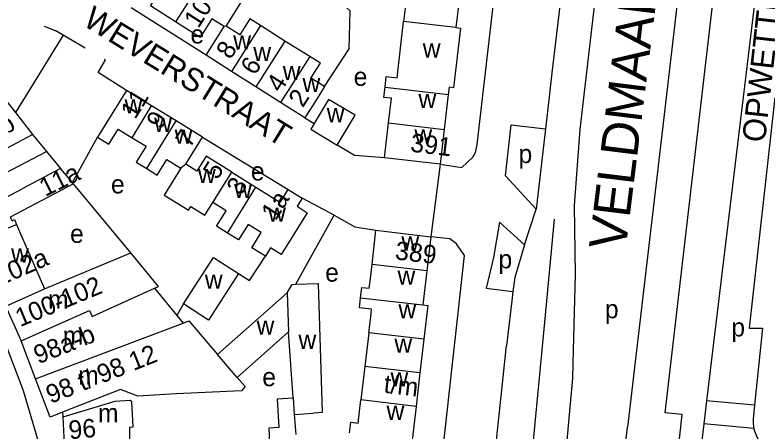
# Model space of a CAD drawing. Extents: x 159902 to 161769, y 383692 to 384875.
# Drawn here: x 161124 to 161287.3, y 384324.5 to 384414.9 of the extents above; entities that cross this region are included whole.
import ezdxf

# ---------------------------------------------------------------- set-up
doc = ezdxf.new("R2010")
doc.units = 0
for name, color, linetype in [('BLT_Basislijn', 7, 'Continuous'), ('BLT_Bebouwing', 7, 'Continuous'), ('BLT_Centroide', 7, 'Continuous'), ('BLT_Huisnummer', 7, 'Continuous'), ('BLT_Huisnummer_ tussenligend', 7, 'Continuous'), ('BLT_Huisnummer_reeks', 7, 'Continuous'), ('BLT_Onderverdeling_panden', 7, 'Continuous'), ('BLT_Straatnaam', 7, 'Continuous'), ('BLT_Straatnaam_hoofdweg', 7, 'Continuous'), ('BLT_Vlakafsluiter', 7, 'Continuous')]:
    doc.layers.add(name, color=color, linetype=linetype)

msp = doc.modelspace()

# ---------------------------------------------------------------- linework, layer by layer
at = {"layer": 'BLT_Basislijn'}
for p, q in [((161271.76, 384452.91), (161264.31, 384389.57)), ((161288.54, 384452.1), (161273.96, 384331.2)), ((161245.38, 384444.89), (161240.42, 384402.37)), ((161252.52, 384442.13), (161246.47, 384390.06)), ((161165.41, 384406.2), (161149.2, 384416.48)), ((161130.28, 384412.54), (161132.67, 384411.6)), ((161134.42, 384410.57), (161124.12, 384393.8)), ((161134.42, 384410.57), (161132.67, 384411.6)), ((161139.21, 384407.76), (161134.42, 384410.57)), ((161240.42, 384402.37), (161239.8, 384397.16)), ((161186.81, 384392.6), (161188.83, 384391.35)), ((161264.31, 384389.57), (161256.78, 384325.49)), ((161136.45, 384378.58), (161141.87, 384388.39)), ((161164.65, 384388.44), (161183.21, 384377.06)), ((161149.12, 384363.32), (161136.67, 384378.32)), ((161193.2, 384371.49), (161186.25, 384375.2)), ((161184.9, 384356.49), (161193.2, 384371.49)), ((161231.98, 384354.91), (161231.71, 384352.88)), ((161160.51, 384352.23), (161159.06, 384349.75)), ((161231.71, 384352.88), (161230.58, 384343.23)), ((161286.06, 384346.97), (161284.36, 384330.24)), ((161226.83, 384308.12), (161230.58, 384343.23)), ((161273.96, 384331.2), (161273.36, 384326.24)), ((161284.36, 384330.24), (161273.96, 384331.2)), ((161284.36, 384330.24), (161284.05, 384327.2)), ((161134.27, 384328.72), (161134.33, 384327.66)), ((161255.4, 384313.8), (161256.78, 384325.49)), ((161284.22, 384325.23), (161273.36, 384326.24))]:
    msp.add_line(p, q, dxfattribs=at)
for points in [[(161216.18, 384382.54), (161220.92, 384381.86), (161223.28, 384384.11), (161223.85, 384385.06), (161224.2, 384386.82), (161237.3, 384500)], [(161262.33, 384305.37), (161262.7, 384308.11), (161266.42, 384307.7), (161268.65, 384328.26), (161265, 384328.62), (161268.94, 384362.86), (161276.08, 384424.55)], [(161191.11, 384399.38), (161196.48, 384407.62), (161196.66, 384415.85), (161195.11, 384417.26)], [(161148.2, 384398.55), (161142.02, 384402.45), (161143.61, 384405.17), (161143.4, 384405.29)], [(161091.04, 384402.68), (161092.89, 384399.78), (161106.05, 384377.98), (161112.13, 384366.07), (161119.42, 384350), (161125.75, 384333.48), (161131.82, 384312.82), (161133.22, 384304.1)], [(161239.8, 384397.16), (161239.01, 384390.24)], [(161288.75, 384397.06), (161283.22, 384346.97), (161286.06, 384346.97)], [(161230.32, 384380.03), (161231.61, 384391.1), (161239.01, 384390.24)], [(161239.01, 384390.24), (161237.03, 384372.81)], [(161246.47, 384390.06), (161245.28, 384373.6), (161245.45, 384358.6), (161245.06, 384342.19), (161244.91, 384336.11), (161242.28, 384307.53)], [(161204.11, 384383.95), (161197.64, 384384.44), (161193.88, 384386.71)], [(161237.03, 384372.81), (161230.32, 384380.03)], [(161193.2, 384371.49), (161197.65, 384368.98), (161202.25, 384368.21)], [(161229.02, 384370), (161227.78, 384362.34), (161226.15, 384355.63), (161231.98, 384354.91)], [(161229.02, 384370), (161234.51, 384365.06)], [(161240.93, 384370.62), (161238.81, 384348.25), (161235.01, 384308.19)], [(161214.46, 384299.39), (161221.43, 384362.75), (161219.74, 384365.24), (161218.3, 384366.34), (161214.15, 384366.82)], [(161234.51, 384365.06), (161232.39, 384357.99), (161231.98, 384354.91)], [(161172.46, 384358.83), (161174.81, 384357.34), (161178.28, 384362.59)], [(161284.05, 384327.2), (161284.05, 384326.42), (161284.14, 384325.64), (161284.22, 384325.23)], [(161273.36, 384326.24), (161270.83, 384305.27), (161270.5, 384302.24)], [(161284.22, 384325.23), (161284.3, 384324.87), (161284.54, 384324.13), (161284.85, 384323.42), (161285.24, 384322.74), (161285.69, 384322.1)]]:
    msp.add_lwpolyline(points, dxfattribs=at)
at = {"layer": 'BLT_Bebouwing'}
for p, q in [((161209.36, 384422.73), (161208.27, 384413.52)), ((161220.64, 384421.12), (161219.6, 384412.2)), ((161165.41, 384406.2), (161169.35, 384412.4)), ((161169.78, 384412.51), (161169.35, 384412.4)), ((161182.53, 384409.25), (161177.22, 384412.62)), ((161187.91, 384405.95), (161182.53, 384409.25)), ((161113.42, 384406.78), (161124.12, 384393.8)), ((161170.92, 384402.7), (161165.41, 384406.2)), ((161176.23, 384399.33), (161170.92, 384402.7)), ((161181.55, 384395.95), (161176.23, 384399.33)), ((161148.2, 384398.55), (161141.87, 384388.39)), ((161153.62, 384395.21), (161148.2, 384398.55)), ((161217.95, 384397.67), (161217.07, 384390.11)), ((161186.81, 384392.6), (161181.55, 384395.95)), ((161124.12, 384393.8), (161127.77, 384389.01)), ((161158.92, 384391.96), (161153.62, 384395.21)), ((161164.65, 384388.44), (161158.92, 384391.96)), ((161204.11, 384383.95), (161204.99, 384391.52)), ((161127.77, 384389.01), (161130.81, 384385.33)), ((161217.07, 384390.11), (161216.18, 384382.54)), ((161161.02, 384382.53), (161164.65, 384388.44)), ((161216.18, 384382.54), (161204.11, 384383.95)), ((161136.45, 384378.58), (161133.87, 384381.64)), ((161170.99, 384380.82), (161176.2, 384377.57)), ((161136.67, 384378.32), (161136.45, 384378.58)), ((161176.2, 384377.57), (161181.41, 384374.31)), ((161183.21, 384377.06), (161186.25, 384375.2)), ((161201.41, 384360.78), (161202.25, 384368.21)), ((161202.25, 384368.21), (161214.15, 384366.82)), ((161214.15, 384366.82), (161213.31, 384359.42)), ((161130.37, 384355.54), (161149.12, 384363.32)), ((161213.31, 384359.42), (161212.46, 384352.02)), ((161154.24, 384355.65), (161159.06, 384349.75)), ((161167.92, 384341.26), (161183, 384354.63)), ((161212.46, 384352.02), (161213.51, 384351.9)), ((161213.51, 384351.9), (161212.66, 384344.6)), ((161159.06, 384349.75), (161160.44, 384348.07)), ((161183.32, 384346.15), (161172.2, 384336.26)), ((161200.72, 384345.99), (161199.86, 384338.69)), ((161128.46, 384335.95), (161125.29, 384344.24)), ((161212.66, 384344.6), (161211.81, 384337.3)), ((161199.86, 384338.69), (161198.99, 384331.4)), ((161211.81, 384337.3), (161210.96, 384330)), ((161184.56, 384328.22), (161188.74, 384328.51)), ((161210.96, 384330), (161210.11, 384322.7)), ((161134.33, 384327.66), (161134.68, 384321.86)), ((161184.56, 384328.22), (161184.86, 384323.88))]:
    msp.add_line(p, q, dxfattribs=at)
for points in [[(161158.8, 384413.44), (161153.37, 384416.89), (161155.14, 384419.68), (161152.24, 384421.52)], [(161169.78, 384412.51), (161173.35, 384418.13), (161168.1, 384421.46), (161166.04, 384418.22), (161163.05, 384420.12)], [(161169.35, 384412.4), (161166.67, 384414.1), (161164.11, 384410.07), (161158.8, 384413.44)], [(161177.22, 384412.62), (161174.92, 384414.09), (161172.73, 384410.64), (161169.78, 384412.51)], [(161204.25, 384399.3), (161204.51, 384401.55), (161206.84, 384401.28), (161208.27, 384413.52)], [(161219.6, 384412.2), (161220.57, 384412.09), (161219.06, 384399.14), (161218.14, 384399.24), (161217.95, 384397.67)], [(161191.11, 384399.38), (161188.17, 384401.24), (161190.23, 384404.48), (161187.91, 384405.95)], [(161191.11, 384399.38), (161189.49, 384396.82), (161186.81, 384392.6)], [(161204.99, 384391.52), (161205.62, 384396.87), (161203.98, 384397.05), (161204.25, 384399.3)], [(161193.88, 384386.71), (161197.73, 384393.16), (161191.97, 384396.61), (161188.83, 384391.35)], [(161188.83, 384391.35), (161188.11, 384390.15), (161193.88, 384386.71)], [(161141.87, 384388.39), (161144.34, 384386.87), (161146.35, 384390.16), (161149.38, 384388.3)], [(161149.38, 384388.3), (161152.4, 384386.44), (161150.28, 384383), (161152.56, 384381.6)], [(161130.81, 384385.33), (161133.87, 384381.64)], [(161170.99, 384380.82), (161165.42, 384384.3), (161163.42, 384381.05), (161161.02, 384382.53)], [(161152.56, 384381.6), (161154.84, 384380.2), (161156.92, 384383.59), (161159.97, 384381.71)], [(161159.97, 384381.71), (161156.36, 384375.83), (161160.62, 384373.22), (161161.62, 384372.6), (161162.1, 384373.37), (161165.14, 384371.47), (161166.88, 384374.25)], [(161136.67, 384378.32), (161122.92, 384371.04), (161123.36, 384370.3), (161123.87, 384370.54), (161124.34, 384369.48)], [(161181.41, 384374.31), (161181.5, 384374.25), (161183.21, 384377.06)], [(161170.09, 384367.62), (161167.7, 384369.09), (161169.78, 384372.47), (161166.88, 384374.25)], [(161186.25, 384375.2), (161185.15, 384373.42), (161187.36, 384372.02), (161184.71, 384367.78), (161181.7, 384362.96), (161179.38, 384364.38), (161178.28, 384362.59)], [(161124.34, 384369.48), (161124.44, 384369.12), (161130.37, 384355.54)], [(161177.37, 384367.74), (161174.52, 384369.49), (161172.47, 384366.15), (161170.09, 384367.62)], [(161178.28, 384362.59), (161175.32, 384364.41), (161177.37, 384367.74)], [(161154.24, 384355.65), (161155.11, 384356.05), (161149.12, 384363.32)], [(161160.51, 384352.23), (161167.04, 384362.33), (161172.46, 384358.83)], [(161198.92, 384353.59), (161199.18, 384355.81), (161200.82, 384355.62), (161201, 384357.16), (161201.41, 384360.78)], [(161172.46, 384358.83), (161165.93, 384348.72), (161160.51, 384352.23)], [(161183, 384354.63), (161184.07, 384356.47), (161184.9, 384356.49)], [(161184.9, 384356.49), (161189.74, 384356.64), (161190.59, 384328.64), (161188.74, 384328.51)], [(161200.72, 384345.99), (161201.13, 384349.44), (161201.32, 384351.07), (161198.66, 384351.38), (161198.92, 384353.59)], [(161125.29, 384344.24), (161125.23, 384344.41), (161122.03, 384351.76)], [(161160.44, 384348.07), (161161.69, 384348.54), (161167.92, 384341.26)], [(161184.31, 384331.83), (161183.32, 384346.15)], [(161134.27, 384328.72), (161131.63, 384327.67), (161128.46, 384335.95)], [(161172.2, 384336.26), (161173.88, 384334.3), (161173.09, 384333.4), (161158.96, 384332.72), (161150.64, 384332.2), (161146.84, 384333.69), (161136.28, 384329.51), (161134.27, 384328.72)], [(161180.81, 384331.62), (161184.31, 384331.83)], [(161148.98, 384331.27), (161145.65, 384331.08), (161134.33, 384327.66)], [(161148.74, 384322.98), (161148.87, 384322.99), (161148.86, 384325.48), (161149.63, 384325.53), (161149.33, 384331.01), (161148.98, 384331.27)], [(161180.81, 384331.62), (161181.18, 384325.43), (161179, 384325.29), (161179.19, 384322.2)], [(161196.52, 384324.28), (161196.78, 384326.55), (161198.39, 384326.36), (161198.99, 384331.4)]]:
    msp.add_lwpolyline(points, dxfattribs=at)
at = {"layer": 'BLT_Onderverdeling_panden'}
for p, q in [((161163.05, 384420.12), (161158.8, 384413.44)), ((161219.6, 384412.2), (161208.27, 384413.52)), ((161177.22, 384412.62), (161170.92, 384402.7)), ((161182.53, 384409.25), (161176.23, 384399.33)), ((161187.91, 384405.95), (161181.55, 384395.95)), ((161204.25, 384399.3), (161217.95, 384397.67)), ((161149.38, 384388.3), (161153.62, 384395.21)), ((161152.56, 384381.6), (161158.92, 384391.96)), ((161204.99, 384391.52), (161217.07, 384390.11)), ((161111.12, 384375.04), (161130.81, 384385.33)), ((161161.02, 384382.53), (161159.97, 384381.71)), ((161166.88, 384374.25), (161170.99, 384380.82)), ((161170.09, 384367.62), (161176.2, 384377.57)), ((161113.32, 384370.83), (161125.51, 384377.2)), ((161115.79, 384366.12), (161124.34, 384369.48)), ((161213.31, 384359.42), (161201.41, 384360.78)), ((161122.03, 384351.76), (161130.37, 384355.54)), ((161183, 384354.63), (161183.32, 384346.15)), ((161198.92, 384353.59), (161212.46, 384352.02)), ((161128.46, 384335.95), (161160.44, 384348.07)), ((161212.66, 384344.6), (161200.72, 384345.99)), ((161172.2, 384336.26), (161167.92, 384341.26)), ((161211.81, 384337.3), (161199.86, 384338.69)), ((161184.31, 384331.83), (161184.56, 384328.22)), ((161210.96, 384330), (161198.99, 384331.4))]:
    msp.add_line(p, q, dxfattribs=at)
for points in [[(161108.6, 384379.66), (161115.33, 384382.43), (161127.77, 384389.01)], [(161133.87, 384381.64), (161125.51, 384377.2)], [(161125.29, 384344.24), (161140.17, 384350.79), (161140.69, 384349.52), (161154.24, 384355.65)]]:
    msp.add_lwpolyline(points, dxfattribs=at)
at = {"layer": 'BLT_Vlakafsluiter'}
for p, q in [((161216.18, 384382.54), (161214.15, 384366.82)), ((161234.51, 384365.06), (161237.03, 384372.81))]:
    msp.add_line(p, q, dxfattribs=at)

# ---------------------------------------------------------------- texts
at = {"layer": 'BLT_Centroide'}
for s, p in [('e', (161162.04, 384408.74)), ('w', (161171.31, 384407.42)), ('w', (161212.41, 384405.69)), ('w', (161175.66, 384404.92)), ('w', (161182.06, 384400.8)), ('e', (161197.43, 384399.56)), ('w', (161186.33, 384398.19)), ('w', (161211.48, 384394.72)), ('w', (161147.75, 384393.58)), ('w', (161191.59, 384391.66)), ('w', (161154.16, 384389.55)), ('w', (161158.61, 384387)), ('w', (161210.59, 384387.03)), ('p', (161233.18, 384382.8)), ('w', (161163.66, 384378.44)), ('e', (161175.14, 384379.02)), ('e', (161144.8, 384376.22)), ('w', (161171.5, 384375.2)), ('w', (161178.87, 384370.06)), ('e', (161135.93, 384365.48)), ('w', (161207.78, 384363.81)), ('w', (161123.14, 384361.22)), ('p', (161228.83, 384359.95)), ('e', (161191.25, 384357.07)), ('w', (161206.94, 384356.41)), ('w', (161165.15, 384355.53)), ('m', (161131.15, 384351.22)), ('w', (161207.14, 384349.09)), ('p', (161251.91, 384349.12)), ('w', (161176.37, 384345.56)), ('p', (161279.33, 384345.17)), ('m', (161134.35, 384343.38)), ('w', (161185.46, 384342.47)), ('w', (161206.26, 384341.66)), ('m', (161137.68, 384334.75)), ('e', (161177.61, 384334.39)), ('w', (161205.41, 384334.34)), ('w', (161204.55, 384327.06)), ('m', (161141.98, 384326.56))]:
    msp.add_text(s, height=4, dxfattribs=at).set_placement(p)
at = {"layer": 'BLT_Huisnummer'}
for s, rotation, p in [('6', 57.5716, (161176.01, 384401.64)), ('2', 57.5684, (161186.41, 384394.66)), ('11', 58.4286, (161150.04, 384392.12)), ('7', 58.4301, (161161.92, 384385.89)), ('5', 58.4301, (161167.88, 384378.98)), ('1a', 58.0043, (161180.5, 384370.09)), ('102a', 23.5543, (161120.71, 384356.1)), ('96', 5.1333, (161135.79, 384322.86))]:
    msp.add_text(s, height=4, rotation=rotation, dxfattribs=at).set_placement(p)
at = {"layer": 'BLT_Huisnummer_ tussenligend'}
for s, rotation, p in [('8', 57.5673, (161170.71, 384405.1)), ('4', 57.5684, (161181.6, 384397.91)), ('9', 58.4212, (161155.61, 384389.92)), ('3', 58.0043, (161172.99, 384375.58))]:
    msp.add_text(s, height=4, rotation=rotation, dxfattribs=at).set_placement(p)
at = {"layer": 'BLT_Huisnummer_reeks'}
for s, rotation, p in [('10-a t/m e', 57.5638, (161163.75, 384411.87)), ('108-a-b', 30.9568, (161108.57, 384380.83)), ('391', 353.3491, (161209.58, 384385.29)), ('11a', 26.3835, (161130.53, 384375.43)), ('389', 353.4886, (161206.29, 384361.9)), ('100-102', 22.5543, (161125.1, 384347.18)), ('98a-b', 21.6602, (161129.02, 384339.13)), ('98 t/ 98 12', 21.658, (161131.69, 384330.53)), ('t/m', 353.3585, (161203.82, 384332.99))]:
    msp.add_text(s, height=4, rotation=rotation, dxfattribs=at).set_placement(p)
at = {"layer": 'BLT_Straatnaam'}
for s, rotation, p in [('OPWETTENSEMOLEN', 83.6113, (161286.62, 384387.12)), ('WEVERSTRAAT', 328.4281, (161138.45, 384412.83))]:
    msp.add_text(s, height=5, rotation=rotation, dxfattribs=at).set_placement(p)
at = {"layer": 'BLT_Straatnaam_hoofdweg'}
msp.add_text('VELDMAARSCHALK MONTGOMERYLAAN', height=8, rotation=82.9908, dxfattribs=at).set_placement((161256.38, 384363.69))

doc.saveas('drawing.dxf')
